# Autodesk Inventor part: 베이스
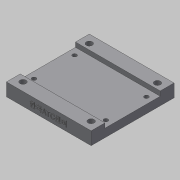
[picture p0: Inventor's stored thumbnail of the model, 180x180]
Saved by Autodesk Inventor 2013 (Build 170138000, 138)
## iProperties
Created: 2020-03
Part Number: 베이스
Material: 일반
Document SubType Name: Modeling
Designer: mduedu
Density: 2.71 g/cm^3
Mass: 221.653 g
Surface Area: 237.875 cm^2
Volume: 81.7908 cm^3
Author: mduedu
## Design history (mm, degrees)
sketch "스케치1"
  geometry: L1 (0, 45)-(-92, 45); L2 (-92, 45)-(-92, -45); L3 (-92, -45)-(0, -45); L4 (0, -45)-(0, 45); 2 further points
  constraints: 8 end point, 2 parallel, 1 coincident, 1 horizontal, 1 midpoint, 1 perpendicular
  dimensions: "d0" = 92 distance of L1.start L1.end; "d2" = 90 distance of L1.end L2.end
extrude "돌출1" new body sketch "스케치1" distance "d3" = 14; taper "d4" = 0 deg
sketch "스케치2"
  geometry: L1 (40, 0)-(50, 0); L2 (50, 0)-(50, 3); L3 (50, 3)-(40, 3); L4 (40, 3)-(40, 0); L5 (15, 14)-(75, 14); L6 (75, 14)-(75, 9); L7 (75, 9)-(15, 9); L8 (15, 9)-(15, 14); L9 (0, 0)-(90, 0) reference; L10 (0, 14)-(90, 14) reference; 3 further points
  constraints: 16 end point, 4 parallel, 2 collinear, 2 horizontal, 2 midpoint, 2 perpendicular, 1 vertical alignment
  dimensions: "d5" = 60 distance of L5.start L5.end; "d7" = 5 distance of L5.end L6.end; "d8" = 10 distance of L1.start L1.end; "d9" = 3 distance of L1.end L2.end
extrude "돌출2" cut sketch "스케치2" stored distance "d10" = 14; taper "d11" = 0 deg
sketch "스케치3"
  geometry: L1 (9, 36)-(83, 36); L2 (83, 36)-(83, -36); L3 (83, -36)-(9, -36); L4 (9, -36)-(9, 36); L5 (92, 30)-(92, -30) reference; 2 further points
  constraints: 8 end point, 2 parallel, 1 horizontal, 1 horizontal alignment, 1 midpoint, 1 perpendicular
  dimensions: "d12" = 72 distance of L1.end L2.end; "d14" = 74 distance of L1.start L1.end; "d15" = 9 distance between parallel lines of L5 L2
hole "구멍1" sketch "스케치3" at (9, -36), (83, -36), (83, 36), (9, 36) diameter "d16" = 6.6; stored, may be unused: countersink angle "d20" = 90 deg, drill point angle "d22" = 118 deg; dims "d17" = 6, "d18" = 4, "d19" = 2, "d21" = 8
sketch "스케치4"
  geometry: L1 (7, 22)-(85, 22); L2 (85, 22)-(85, -22); L3 (85, -22)-(7, -22); L4 (7, -22)-(7, 22); L5 (0, -45)-(0, 45) reference; L6 (92, 45)-(92, -45) reference; 5 further points
  constraints: 8 end point, 2 parallel, 1 horizontal, 1 horizontal alignment, 1 midpoint, 1 perpendicular
  dimensions: "d26" = 7 distance between parallel lines of L4 L5; "d27" = 7 distance between parallel lines of L6 L2; "d28" = 44 distance of L1.end L2.end
hole "구멍2" sketch "스케치4" at (7, 22), (85, 22), (85, -22), (7, -22) diameter "d29" = 4.5; stored, may be unused: countersink angle "d33" = 90 deg, drill point angle "d35" = 118 deg; dims "d30" = 6, "d31" = 8, "d32" = 4.4, "d34" = 8
sketch "스케치5"
  geometry: L1 (0, 0)-(92, 0) reference; 5 further points
  constraints: 3 coincident, 1 midpoint, 1 vertical alignment, 1 other
  dimensions: "d36" = 7 distance of point (46, 7) point (46, 0)
feature "엠보싱1" sketch "스케치5" dims "d3" = 14, "d37" = 0.5, "d38" = 0
node "솔리드1"
